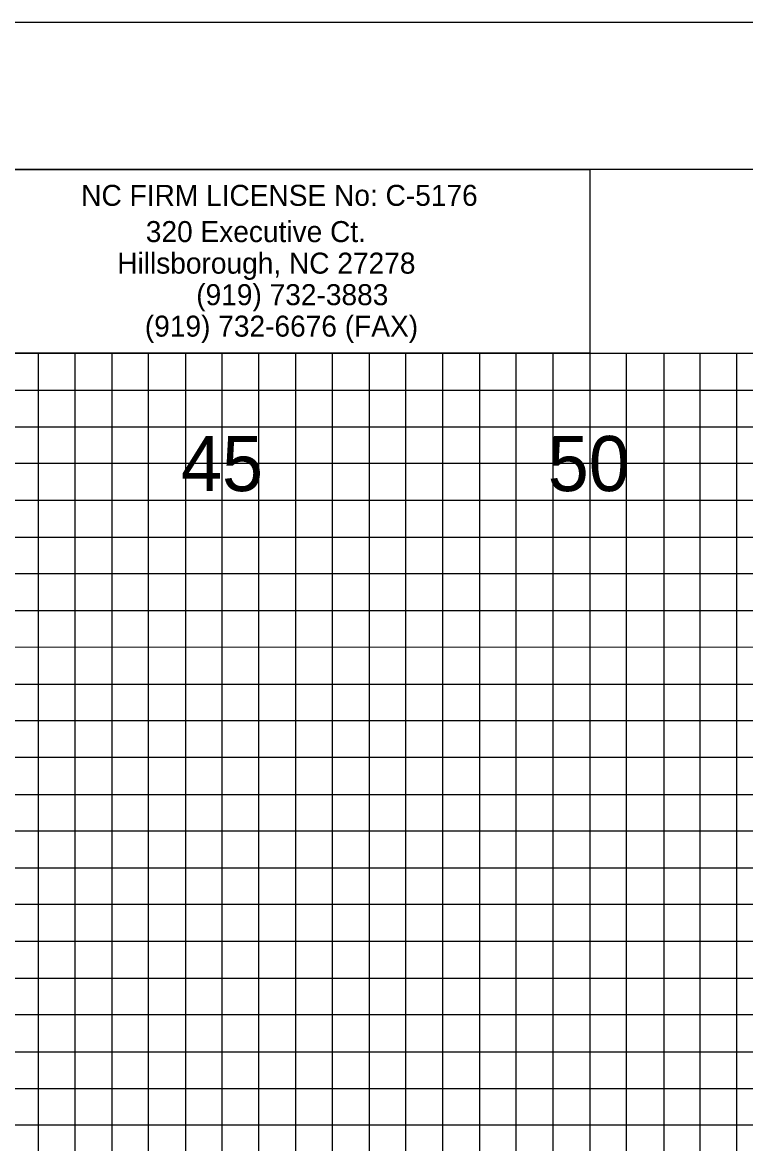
# Model space of a CAD drawing. Extents: x -7 to 162, y -2 to 107.
# Drawn here: x 122.28 to 132.12, y 91.75 to 107 of the extents above; entities that cross this region are included whole.
import ezdxf

# ---------------------------------------------------------------- set-up
doc = ezdxf.new("R2010")
doc.units = 0
for name, color, linetype in [('Prop DSN Text', 7, 'Continuous'), ('Prop XS Offset Labels', 7, 'Continuous'), ('Sheet Block Title CELL', 7, 'Continuous'), ('Sheet Cross Section CELL', 7, 'Continuous'), ('Sheet Cross Section Grid Major CELL', 7, 'Continuous'), ('Sheet Cross Section Grid Middle CELL', 7, 'Continuous'), ('Sheet Cross Section Grid Minor 1 CELL', 7, 'Continuous'), ('Sheet Cross Section Grid Minor 2 CELL', 7, 'Continuous'), ('Sheet Plot Border Inside CELL', 7, 'Continuous'), ('Sheet Plot Border Outside CELL', 7, 'Continuous')]:
    doc.layers.add(name, color=color, linetype=linetype)

msp = doc.modelspace()

# ---------------------------------------------------------------- linework, layer by layer
at = {"layer": 'Sheet Block Title CELL'}
msp.add_lwpolyline([(110.951, 105), (130, 105), (130, 102.5), (110.951, 102.5)], close=True, dxfattribs=at)
at = {"layer": 'Sheet Cross Section CELL'}
for points in [[(160, 105), (0, 105), (0, 0), (160, 0)], [(140, 105), (130, 105), (130, 102.5), (140, 102.5)]]:
    msp.add_lwpolyline(points, close=True, dxfattribs=at)
at = {"layer": 'Sheet Cross Section Grid Major CELL'}
for p, q in [((125, 105), (120, 105)), ((130, 105), (130, 0)), ((125, 0), (125, 102.5))]:
    msp.add_line(p, q, dxfattribs=at)
for points in [[(160, 102.5), (160, 95), (0, 95)], [(0, 100), (160, 100)]]:
    msp.add_lwpolyline(points, dxfattribs=at)
at = {"layer": 'Sheet Cross Section Grid Middle CELL'}
for points in [[(117.5, 105), (122.5, 105)], [(127.5, 105), (129.965, 105), (130, 105), (130, 102.5), (132.495, 102.5), (132.495, 0), (137.5, 0), (137.5, 102.5), (140, 102.5)], [(0, 102.5), (137.5, 102.5)], [(0, 92.5), (160, 92.5), (160, 102.5)], [(122.5, 102.5), (122.5, 0), (127.5, 0), (127.5, 102.5)], [(160, 97.5), (0, 97.5)]]:
    msp.add_lwpolyline(points, dxfattribs=at)
at = {"layer": 'Sheet Cross Section Grid Minor 1 CELL'}
for p, q in [((130, 104.5), (130, 103.99)), ((130, 103.5), (130, 102.945)), ((0, 102), (160, 102))]:
    msp.add_line(p, q, dxfattribs=at)
for points in [[(0, 101.5), (135, 101.5), (160, 101.5)], [(160, 101), (0, 101)], [(0, 100.5), (160, 100.5)], [(160, 99.5), (0, 99.5)], [(0, 99), (160, 99)], [(160, 98.5), (0, 98.49)], [(0, 98), (160, 98)], [(160, 97), (0, 97)], [(0, 96.5), (160, 96.5), (160, 96), (0, 96)], [(0, 95.5), (160, 95.5), (160, 94.5), (0, 94.5)], [(0, 94), (160, 94), (160, 93.5), (0, 93.5)], [(0, 93), (160, 93), (160, 92), (0, 92)]]:
    msp.add_lwpolyline(points, dxfattribs=at)
at = {"layer": 'Sheet Cross Section Grid Minor 2 CELL'}
for points in [[(123, 105), (123.5, 105)], [(124, 105), (124.5, 105)], [(125.5, 105), (126, 105)], [(126.5, 105), (127, 105)], [(128, 105), (128.5, 105)], [(129, 105), (129.5, 105)], [(122.5, 0), (123, 0), (123, 102.5)], [(123.5, 102.5), (123.5, 0)], [(123.5, 0), (124, 0), (124, 102.5)], [(124.5, 102.5), (124.5, 0)], [(125, 0), (125.5, 0), (125.5, 102.5)], [(126, 102.5), (126, 0)], [(126, 0), (126.5, 0), (126.5, 102.5)], [(127, 102.5), (127, 0)], [(127.5, 0), (128, 0), (128, 102.5)], [(128.5, 102.5), (128.5, 0)], [(128.5, 0), (129, 0), (129, 102.5)], [(129.5, 102.5), (129.5, 0)], [(130, 0), (130.5, 0), (130.5, 102.5), (131.01, 102.5), (131.01, 0)], [(131, 0), (131.5, 0), (131.5, 102.5), (131.995, 102.5), (131.995, 0)]]:
    msp.add_lwpolyline(points, dxfattribs=at)
at = {"layer": 'Sheet Plot Border Inside CELL'}
msp.add_lwpolyline([(-5.4, -0.5), (161.2, -0.5), (161.2, 105), (-5.4, 105)], close=True, dxfattribs=at)
at = {"layer": 'Sheet Plot Border Outside CELL'}
msp.add_lwpolyline([(-6.7, -2.5), (161.65, -2.5), (161.65, 107), (-6.7, 107)], close=True, dxfattribs=at)

# ---------------------------------------------------------------- texts
at = {"layer": 'Prop DSN Text'}
for s, p in [('NC FIRM LICENSE No: C-5176', (123.083, 104.505)), ('320 Executive Ct.', (123.962, 104.012)), ('Hillsborough, NC 27278', (123.573, 103.583)), ('(919) 732-3883', (124.648, 103.154)), ('(919) 732-6676 (FAX)', (123.949, 102.726))]:
    msp.add_text(s, height=0.28573, rotation=360, dxfattribs=at).set_placement(p)
at = {"layer": 'Prop XS Offset Labels'}
for s, p in [('45', (124.441, 100.625)), ('50', (129.429, 100.625))]:
    msp.add_text(s, height=0.75, dxfattribs=at).set_placement(p)

doc.saveas('drawing.dxf')
